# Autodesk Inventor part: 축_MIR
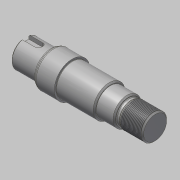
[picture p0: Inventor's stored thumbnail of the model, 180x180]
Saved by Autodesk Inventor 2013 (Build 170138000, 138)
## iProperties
Created: 2019-05
Part Number: 축_MIR
Material: 강철, 연강
Document SubType Name: Modeling
Designer: user
Density: 7.86 g/cm^3
Author: mduedu
d0: 102.000 mm
d2: 21.000 mm
d3: 14.000 mm
d4: 30.000 mm
d5: 17.000 mm
d6: 22.000 mm
d7: 28.000 mm
d8: 25.000 mm
d9: 22.000 mm
d10: 20.000 mm
d12: 2.340 mm
d14: 30.00 deg
d15: 2.000 mm
d16: 1.000 mm
d17: 0.300 mm
d18: 1.000 mm
d21: 18.400 mm
d23: 2.340 mm
d24: 30.00 deg
d26: 0.600 mm
d27: 1.000 mm
d32: 1.000 mm
d35: 14.000 mm
d37: 6.000 mm
d38: 3.500 mm
d39: 0.00 deg
d40: 1.000 mm
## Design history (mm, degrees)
derived "축.ipt"
  sketch "스케치1"
    geometry: L1 (0, 0)-(-20, 0) reference; L2 (-20, 0)-(-20, 11) reference; L3 (-20, 11)-(0, 11) reference; L4 (0, 11)-(0, 0) reference; L5 (-20, 0)-(-37, 0) reference; L6 (-37, 0)-(-37, 14) reference; L7 (-37, 14)-(-20, 14) reference; L8 (-20, 14)-(-20, 0) reference; L9 (-37, 0)-(-67, 0) reference; L10 (-67, 0)-(-67, 12.5) reference; L11 (-67, 12.5)-(-37, 12.5) reference; L12 (-37, 12.5)-(-37, 0) reference; L13 (-67, 0)-(-81, 0) reference; L14 (-81, 0)-(-81, 11) reference; L15 (-81, 11)-(-67, 11) reference; L16 (-67, 11)-(-67, 0) reference; L17 (-81, 0)-(-102, 0) reference; L18 (-102, 0)-(-102, 10) reference; L19 (-102, 10)-(-81, 10) reference; L20 (-81, 10)-(-81, 0) reference
  sketch "스케치2"
    geometry: L1 (-20.5, 12.938)-(-21.876, 13.732) reference; L2 (-22.876, 14)-(-37, 14) reference; L3 (-37, 14)-(-37, 12.8) reference; L4 (-37.3, 12.5)-(-66, 12.5) reference; L5 (-66, 12.5)-(-67, 11.5) reference; L6 (-67, 11.5)-(-67, 11) reference; L7 (-67, 11)-(-81, 11) reference; L8 (-81, 11)-(-81, 10) reference; L9 (-81, 10)-(-102, 10) reference; L10 (-102, 10)-(-102, -10) reference; L11 (0, 0)-(-102, 0) reference; L12 (-81, 10)-(-84.726, 10) reference; L13 (-83.34, 9.2)-(-81, 9.2) reference; L14 (-81, 9.2)-(-81, 10) reference; L15 (-84.726, 10)-(-83.34, 9.2) reference; L16 (-102, -10)-(-81, -10) reference; L17 (-81, -10)-(-81, -11) reference; L18 (-81, -11)-(-67, -11) reference; L19 (-67, -11)-(-67, -11.5) reference; L20 (-67, -11.5)-(-66, -12.5) reference; L21 (-66, -12.5)-(-37.3, -12.5) reference; L22 (-37, -12.8)-(-37, -14) reference; L23 (-37, -14)-(-22.876, -14) reference; L24 (-21.876, -13.732)-(-20.5, -12.938) reference; L25 (-20, -12.072)-(-20, -11) reference; L26 (-20, -11)-(0, -11) reference; L27 (0, -11)-(0, 11) reference; L28 (0, 11)-(-20, 11) reference; L29 (-20, 11)-(-20, 12.072) reference; A1 r 1 centre (-21, 12.072) between (-20, 12.072) and (-20.5, 12.938) reference; A2 r 2 centre (-22.876, 12) between (-21.876, 13.732) and (-22.876, 14) reference; A3 r 0.3 centre (-37.3, 12.8) between (-37.3, 12.5) and (-37, 12.8) reference; A4 r 0.3 centre (-37.3, -12.8) between (-37, -12.8) and (-37.3, -12.5) reference; A5 r 2 centre (-22.876, -12) between (-22.876, -14) and (-21.876, -13.732) reference; A6 r 1 centre (-21, -12.072) between (-20.5, -12.938) and (-20, -12.072) reference
  sketch "스케치3"
    geometry: L1 (-10, -3)-(1, -3) reference; L2 (1, -3)-(1, 3) reference; L3 (1, 3)-(-10, 3) reference; L4 (-10, 3)-(-10, -3) reference; 3 further points
    constraints: 1 vertical alignment
  node "작업 평면1"
feature "솔리드1::축.ipt"
tag "피쳐 태그1"
node "솔리드1"
other parameters: "d0" = 10, "d0_1" = 102, "d2" = 21, "d3" = 14, "d4" = 30, "d5" = 17, "d6" = 22, "d7" = 28, "d8" = 25, "d9" = 22, "d10" = 20, "d12" = 2.34, "d14" = 30 deg, "d15" = 2, "d16" = 1, "d17" = 0.3, "d18" = 1, "d21" = 18.4, "d23" = 2.34, "d24" = 30 deg, "d26" = 0.6, "d27" = 1, "d32" = 1, "d35" = 14, "d37" = 6, "d38" = 3.5, "d39" = 0 deg, "d40" = 1
